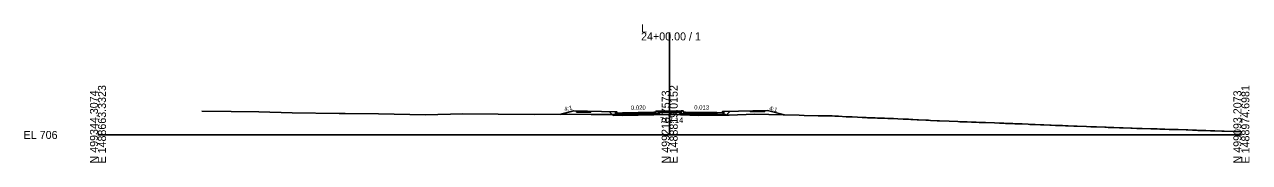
# Model space of a CAD drawing. Extents: x -26 to 4203, y -10 to 9538.
# Drawn here: x 974.3 to 1402.8, y 2990.3 to 3038.8 of the extents above; entities that cross this region are included whole.
import ezdxf

# ---------------------------------------------------------------- set-up
doc = ezdxf.new("R2010")
doc.units = 0
for name, color, linetype in [('Default', 7, 'Continuous'), ('Exist Horizontal Alignment', 7, 'Continuous'), ('Prop Grid Mask', 7, 'Continuous'), ('Prop Horizontal Alignment', 7, 'Continuous'), ('Prop Horizontal Alignment Curve and Spiral Data', 7, 'Continuous'), ('Prop Horizontal Alignment Station Label', 7, 'Continuous'), ('Prop Horizontal Alignment Tick Label', 7, 'Continuous'), ('Prop Horizontal Alignment Tick Large', 7, 'Continuous'), ('Prop Horizontal Alignment Tick Small', 7, 'Continuous'), ('Scratch_Level_4', 7, 'Continuous'), ('Scratch_Level_5', 7, 'Continuous'), ('Sheet Border Standard 30in CELL', 7, 'Continuous'), ('Sheet Data Field CELL', 7, 'Continuous'), ('Sheet Plot Border Inside CELL', 7, 'Continuous'), ('Sheet Plot Border Outside CELL', 7, 'Continuous')]:
    doc.layers.add(name, color=color, linetype=linetype)

msp = doc.modelspace()

# ---------------------------------------------------------------- linework, layer by layer
at = {"layer": 'Exist Horizontal Alignment'}
msp.add_lwpolyline([(1036.39, 3008.33), (1046.56, 3008.26), (1056.25, 3008.16), (1067.93, 3007.78), (1084.44, 3007.58), (1086.43, 3007.55), (1098.11, 3007.43), (1114.57, 3007.11), (1127.59, 3007.36), (1139.99, 3007.27), (1152.89, 3007.14), (1165, 3007.24), (1172.58, 3007.15), (1184.1, 3007.23), (1196.6, 3007.21), (1197.39, 3007.21), (1200, 3007.14), (1203.77, 3007.05), (1210.24, 3006.85), (1216.55, 3006.99), (1220.84, 3006.94), (1229.62, 3007.26), (1239.73, 3007.07), (1245.27, 3006.99), (1247, 3006.81), (1251.97, 3006.65), (1252.69, 3006.68), (1255.17, 3006.67), (1256.83, 3006.67), (1257.76, 3006.63), (1258.49, 3006.59), (1259.07, 3006.57), (1261.74, 3006.41), (1262.29, 3006.38), (1263.82, 3006.31), (1265.72, 3006.22), (1267.38, 3006.13), (1268.71, 3006.08), (1269.15, 3006.06), (1269.7, 3006.04), (1270.93, 3005.99), (1271.92, 3005.96), (1272.71, 3005.93), (1273.69, 3005.89), (1275.13, 3005.84), (1276.27, 3005.81), (1277.67, 3005.75), (1278.34, 3005.72), (1279.82, 3005.67), (1281.65, 3005.59), (1283.55, 3005.49), (1284.31, 3005.45), (1285.06, 3005.42), (1286.61, 3005.33), (1287.05, 3005.3), (1289.62, 3005.18), (1290.49, 3005.13), (1291.19, 3005.1), (1293.6, 3004.98), (1294.4, 3004.95), (1297.76, 3004.81), (1300.83, 3004.68), (1301.56, 3004.65), (1302.93, 3004.6), (1304.04, 3004.56), (1305.55, 3004.51), (1307.25, 3004.44), (1308.27, 3004.4), (1309.53, 3004.36), (1310.05, 3004.34), (1310.46, 3004.33), (1313.67, 3004.23), (1315.38, 3004.15), (1316.88, 3004.09), (1317.49, 3004.06), (1320.1, 3003.97), (1320.71, 3003.95), (1321.48, 3003.92), (1323.31, 3003.85), (1325.46, 3003.76), (1326.05, 3003.72), (1326.52, 3003.71), (1327.82, 3003.66), (1329.73, 3003.59), (1330.94, 3003.53), (1332.94, 3003.44), (1333.43, 3003.42), (1334.94, 3003.36), (1336.15, 3003.31), (1336.71, 3003.29), (1337.41, 3003.26), (1338.49, 3003.22), (1339.37, 3003.19), (1341.39, 3003.12), (1342.05, 3003.09), (1342.58, 3003.07), (1345.79, 3002.95), (1347.38, 3002.89), (1349.35, 3002.81), (1352.21, 3002.71), (1352.72, 3002.68), (1353.34, 3002.66), (1354.49, 3002.62), (1355.42, 3002.59), (1357.32, 3002.52), (1358.64, 3002.48), (1361.3, 3002.39), (1361.85, 3002.37), (1363.38, 3002.32), (1365.28, 3002.26), (1368.27, 3002.16), (1368.72, 3002.14), (1369.27, 3002.13), (1370.49, 3002.09), (1371.48, 3002.06), (1373.25, 3002.01), (1374.7, 3001.96), (1377.23, 3001.89), (1377.91, 3001.87), (1380.71, 3001.77), (1381.22, 3001.75), (1382.94, 3001.68), (1384.33, 3001.63), (1384.72, 3001.62), (1385.2, 3001.6), (1387.54, 3001.51), (1389.18, 3001.46), (1390.05, 3001.43), (1390.75, 3001.4), (1393.16, 3001.32), (1393.96, 3001.29), (1397.31, 3001.18), (1400, 3001.09)], dxfattribs=at)
at = {"layer": 'Prop Horizontal Alignment Curve and Spiral Data'}
for points in [[(1183.5, 3006.9), (1180.24, 3006.84), (1178.92, 3008.16)], [(1194.5, 3007.08), (1183.5, 3006.86)], [(1183.5, 3006.86), (1183.5, 3006.9)], [(1196.76, 3007.17), (1194.5, 3007.12)], [(1194.5, 3007.12), (1194.5, 3007.08)], [(1194.5, 3007.08), (1194.5, 3007.08)], [(1196.76, 3007.17), (1203.24, 3007.2)], [(1203.24, 3007.2), (1205.5, 3007.16)], [(1205.5, 3007.16), (1205.5, 3007.12)], [(1205.5, 3007.12), (1216.5, 3006.97)], [(1205.5, 3007.12), (1205.5, 3007.12)], [(1216.5, 3007.01), (1219.75, 3006.97), (1221.06, 3008.28)], [(1216.5, 3006.97), (1216.5, 3007.01)]]:
    msp.add_lwpolyline(points, dxfattribs=at)
at = {"layer": 'Prop Horizontal Alignment Station Label'}
for p, q in [((1166.38, 3008.41), (1161.59, 3007.21)), ((1234.25, 3008.54), (1240.17, 3007.06))]:
    msp.add_line(p, q, dxfattribs=at)
for points in [[(1181, 3008.12), (1166.38, 3008.41)], [(1219, 3008.24), (1234.25, 3008.54)]]:
    msp.add_lwpolyline(points, dxfattribs=at)
at = {"layer": 'Prop Horizontal Alignment Tick Label'}
for points in [[(1183.5, 3007.49), (1183.5, 3007.24)], [(1194.5, 3007.46), (1194.5, 3007.71)], [(1205.5, 3007.74), (1216.5, 3007.6)], [(1205.5, 3007.49), (1205.5, 3007.74)], [(1216.5, 3007.35), (1205.5, 3007.49)], [(1216.5, 3007.6), (1216.5, 3007.35)]]:
    msp.add_lwpolyline(points, dxfattribs=at)
at = {"layer": 'Prop Horizontal Alignment Tick Large'}
for points in [[(1194.5, 3007.46), (1183.5, 3007.24)], [(1183.5, 3007.24), (1183.5, 3006.86)], [(1194.5, 3007.08), (1194.5, 3007.46)], [(1205.5, 3007.49), (1216.5, 3007.35)], [(1205.5, 3007.12), (1205.5, 3007.49)], [(1216.5, 3006.97), (1205.5, 3007.12)], [(1216.5, 3007.35), (1216.5, 3006.97)]]:
    msp.add_lwpolyline(points, dxfattribs=at)
at = {"layer": 'Prop Horizontal Alignment Tick Small'}
for p, q in [((1167.38, 3008.05), (1167.38, 3008.39)), ((1228.25, 3008.09), (1228.25, 3008.42)), ((1233.25, 3008.19), (1233.25, 3008.52)), ((1172.38, 3007.95), (1167.38, 3008.05)), ((1172.38, 3007.95), (1172.38, 3008.29)), ((1196.01, 3007.97), (1203.99, 3008.01)), ((1228.25, 3008.09), (1233.25, 3008.19))]:
    msp.add_line(p, q, dxfattribs=at)
for points in [[(1194.5, 3007.96), (1195.25, 3007.97), (1195.25, 3008.39), (1196.01, 3008.39)], [(1196.01, 3008.39), (1203.99, 3008.42)], [(1196.01, 3008.39), (1196.01, 3007.4)], [(1203.99, 3008.42), (1203.99, 3007.44)], [(1183.5, 3007.74), (1181.5, 3007.62), (1181.5, 3008.12), (1181, 3008.12)], [(1181, 3008.12), (1181, 3007.1), (1183.5, 3007.15)], [(1183.5, 3007.15), (1183.5, 3007.74)], [(1194.5, 3007.37), (1194.5, 3007.96)], [(1196.01, 3007.4), (1194.5, 3007.37)], [(1203.99, 3007.44), (1205.5, 3007.41)], [(1205.5, 3007.41), (1205.5, 3007.99)], [(1216.5, 3007.85), (1218.5, 3007.74), (1218.5, 3008.24), (1219, 3008.24)], [(1219, 3008.24), (1219, 3007.23), (1216.5, 3007.26)], [(1216.5, 3007.26), (1216.5, 3007.85)]]:
    msp.add_lwpolyline(points, dxfattribs=at)
at = {"layer": 'Scratch_Level_4'}
for p, q in [((1200, 3000), (1200, 3035.98)), ((1000, 3000), (1200, 3000)), ((1200, 3000), (1400, 3000))]:
    msp.add_line(p, q, dxfattribs=at)
at = {"layer": 'Sheet Border Standard 30in CELL'}
for points in [[(1194.5, 3007.96), (1183.5, 3007.74)], [(1205.5, 3007.99), (1216.5, 3007.85)]]:
    msp.add_lwpolyline(points, dxfattribs=at)
at = {"layer": 'Sheet Data Field CELL'}
for points in [[(1183.5, 3007.15), (1180.5, 3007.09), (1180.24, 3006.84)], [(1180.24, 3006.84), (1183.5, 3006.9)], [(1183.5, 3006.9), (1183.5, 3007.15)], [(1194.5, 3007.37), (1196.51, 3007.41), (1196.76, 3007.17)], [(1194.5, 3007.12), (1194.5, 3007.37)], [(1196.76, 3007.17), (1194.5, 3007.12)], [(1205.5, 3007.41), (1203.49, 3007.45), (1203.24, 3007.2)], [(1203.24, 3007.2), (1205.5, 3007.16)], [(1205.5, 3007.16), (1205.5, 3007.41)], [(1216.5, 3007.26), (1219.5, 3007.22), (1219.75, 3006.97)], [(1216.5, 3007.01), (1216.5, 3007.26)], [(1219.75, 3006.97), (1216.5, 3007.01)]]:
    msp.add_lwpolyline(points, dxfattribs=at)
at = {"layer": 'Sheet Plot Border Inside CELL'}
for points in [[(1194.5, 3007.96), (1183.5, 3007.74)], [(1183.5, 3007.74), (1183.5, 3007.49)], [(1183.5, 3007.49), (1194.5, 3007.71)], [(1194.5, 3007.71), (1194.5, 3007.96)], [(1194.5, 3007.71), (1194.5, 3007.71), (1194.5, 3007.71)], [(1205.5, 3007.99), (1216.5, 3007.85)], [(1205.5, 3007.74), (1205.5, 3007.99)], [(1216.5, 3007.6), (1205.5, 3007.74)], [(1205.5, 3007.74), (1205.5, 3007.74), (1205.5, 3007.74)], [(1216.5, 3007.85), (1216.5, 3007.6)]]:
    msp.add_lwpolyline(points, dxfattribs=at)
at = {"layer": 'Sheet Plot Border Outside CELL'}
for points in [[(1205.5, 3007.99), (1204.75, 3008.01), (1204.75, 3008.42), (1203.99, 3008.42)], [(1181.5, 3007.62), (1181.5, 3008.12), (1181, 3008.12)], [(1183.5, 3007.74), (1181.5, 3007.62)], [(1216.5, 3007.85), (1218.5, 3007.74)], [(1218.5, 3007.74), (1218.5, 3008.24), (1219, 3008.24)]]:
    msp.add_lwpolyline(points, dxfattribs=at)

# ---------------------------------------------------------------- texts
at = {"layer": 'Default'}
msp.add_text('-', height=0.0001, dxfattribs=at).set_placement((1000, 3000))
msp.add_text('-', height=0.0001, dxfattribs=at).set_placement((1000, 3000))
msp.add_text('-', height=0.0001, dxfattribs=at).set_placement((1000, 3000))
at = {"layer": 'Prop Grid Mask'}
for rotation, p in [(14.0362, (1163.3, 3008.24)), (345.9638, (1234.72, 3008.73))]:
    msp.add_text('4:1', height=1.5, rotation=rotation, dxfattribs=at).set_placement(p)
at = {"layer": 'Prop Horizontal Alignment'}
msp.add_text('713.14', height=2, dxfattribs=at).set_placement((1196.6, 3004.19))
at = {"layer": 'Scratch_Level_4'}
for s, p in [('L', (1190, 3035.98)), ('24+00.00 / 1', (1190, 3033.18)), ('EL 706', (974, 2998.6))]:
    msp.add_text(s, height=2.8, dxfattribs=at).set_placement(p)
for s, p in [('E 1488663.3323', (1002.8, 2990)), ('E 1488819.0152', (1202.8, 2990)), ('E 1488974.6981', (1402.8, 2990)), ('N 499344.3074', (1000, 2990)), ('N 499218.7573', (1200, 2990)), ('N 499093.2073', (1400, 2990))]:
    msp.add_text(s, height=2.8, rotation=90, dxfattribs=at).set_placement(p)
at = {"layer": 'Scratch_Level_5'}
for s, rotation, p in [('0.020', 1.1458, (1186.47, 3008.8)), ('0.013', 359.2361, (1208.59, 3008.95))]:
    msp.add_text(s, height=1.5, rotation=rotation, dxfattribs=at).set_placement(p)

doc.saveas('drawing.dxf')
